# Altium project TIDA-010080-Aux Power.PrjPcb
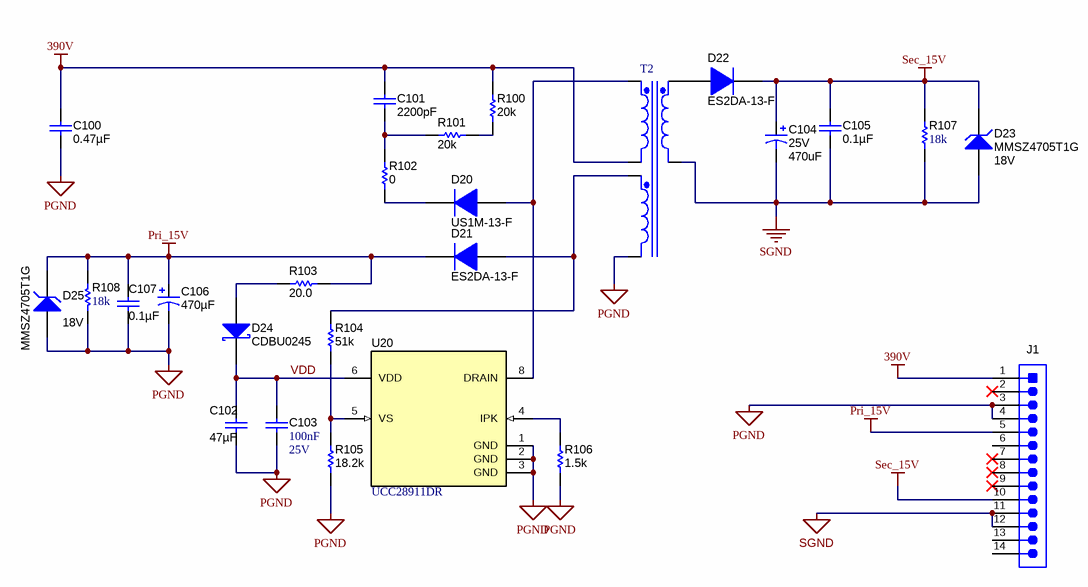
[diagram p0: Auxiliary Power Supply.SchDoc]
EVM_Orderable: N/A; PCB_Rev: E1; PRJ_Customer: Public Release; PRJ_Engineer: Max Wang; PRJ_Number: TIDA-010080-Aux; SCH_Rev: E1; TechSupport: http://www.ti.com/support; TID: TIDA-010080-Aux
3 sheets, 32 parts. Net scope: global (net labels, ports and power ports of the same name join across sheets).
Board file: Auxiliary Power Supply.pcbdoc
Sheets:
  Auxiliary Power Supply.SchDoc
  CoverSheet.SchDoc
  Hardware.SchDoc

## Sheet Auxiliary Power Supply.SchDoc
size 431 x 279 mm; PageSetup: Record=PageOptions¦CenterHorizontal=True¦CenterVertical=True¦PrintScale=1.00¦XCorrection=1.00¦YCorrection=1.00¦PrintKind=0¦BorderSize=5000000¦LeftOffset=0¦BottomOffset=0¦Orientation=2¦PaperLength=1000¦PaperWidth=1000¦Scale=100¦PaperSource=15¦PrintQuality=600¦MediaType=1¦DitherType=10¦PaperKind=Letter¦PrintScaleMode=1; TID#: TIDA-010081_AUX

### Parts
C100  ValueDisplayed: 0.47µF  [ECWFD_1260x650x1270]  (hidden comment: ECW-FD2W474Q1)
C101  ValueDisplayed: 2200pF  [1206]  (hidden comment: GRM31BR72J222KW01L)
C102  ValueDisplayed: 47µF  [1206_190]  (hidden comment: C3216X5R1E476M160AC)
C103  Cap_F: 100nF  VDC_V: 25V  [0603]  (hidden comment: GRM188R71E104KA01D)
C104  VDC_V: 25V  ValueDisplayed: 470uF  [Chemi-Con_1000x1600]  (hidden comment: ELXZ250ELL471MJ16S)
C105  ValueDisplayed: 0.1µF  [0603]  (hidden comment: C0603C104K3RACTU)
C106  ValueDisplayed: 470µF  [Chemi-Con_1000x1600]  (hidden comment: ELXZ250ELL471MJ16S)
C107  ValueDisplayed: 0.1µF  [0603]  (hidden comment: C0603C104K3RACTU)
D20  US1M-13-F  [SMA]
D21  ES2DA-13-F  [SMA]
D22  ES2DA-13-F  [SMA]
D23  MMSZ4705T1G  value 18V  [SOD-123]
D24  CDBU0245  [SOD-523F]
D25  MMSZ4705T1G  value 18V  [SOD-123]
J1  TSW-114-08-L-S-RA  [TE_4-644694-4]  (value not drawn)
R100  ValueDisplayed: 20k  [1206]  (hidden comment: CRCW120620K0JNEA)
R101  ValueDisplayed: 20k  [1206]  (hidden comment: CRCW120620K0JNEA)
R102  ValueDisplayed: 0  [0805_HV]  (hidden comment: CRCW08050000Z0EA)
R103  ValueDisplayed: 20.0  [1206L]  (hidden comment: CRCW120620R0FKEA)
R104  ValueDisplayed: 51k  [0603]  (hidden comment: CRCW060351K0JNEA)
R105  ValueDisplayed: 18.2k  [0805_HV1]  (hidden comment: CRCW080518K2FKEA)
R106  ValueDisplayed: 1.5k  [0603]  (hidden comment: CRCW06031K50JNEA)
R107  ValueDisplayed: 18k  [0603]  (hidden comment: CRCW060318K0JNEA)
R108  ValueDisplayed: 18k  [0603]  (hidden comment: CRCW060318K0JNEA)
T2  750344399  [Fly_T1]  (value not drawn)
U20  UCC28911DR  [D0007A_N]

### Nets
390V: C100.1 C101.1 J1.1 R100.2 T2.4(Sec1-)
PGND: C100.2 C102.2 C103.2 C106.2(-) C107.2 D25.2(A) J1.3 J1.4 R105.1 R106.1 R108.1 T2.6(Sec2-) U20.1(GND) U20.2(GND) U20.3(GND)
Pri_15V: C106.1(+) C107.1 D21.1(K) D25.1(K) J1.5 R103.1 R108.2
Sec_15V: C104.1(+) C105.1 D22.1(K) D23.1(K) J1.10 R107.2
SGND: C104.2(-) C105.2 D23.2(A) J1.11 J1.12 R107.1 T2.2(Pri-)
VDD: C102.1 C103.1 D24.1(K) U20.6(VDD)
NetC101_2: C101.2 R101.2 R102.2
NetD20_1: D20.1(K) R102.1
NetD20_2: D20.2(A) T2.3(Sec1+) U20.8(DRAIN)
NetD21_2: D21.2(A) R104.2 T2.5(Sec2+)
NetD22_2: D22.2(A) T2.1(Pri+)
NetD24_2: D24.2(A) R103.2
NetR100_1: R100.1 R101.1
NetR104_1: R104.1 R105.2 U20.5(VS)
NetR106_2: R106.2 U20.4(IPK)

Not connected (* = marked no-connect by the designer): J1 2* 6 7* 8* 9* 13 14

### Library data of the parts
C100 = ECW-FD2W474Q1: CAP, Film, 0.47 µF, 450 V, +/- 10%, TH; Manufacturer: Panasonic; Polarized: N; CompType: Capacitor; Value: 0.47uF; U/M: EA; Cap_F: 0.00000047; Tolerance_%: 10; Value1: Unknown; VDC_V: 450; Value2: 450V; TaMin_C: -40; TaMax_C: 110; Cap_Case: 12.6x6.5x12.7mm; AEC Category: Q200
C101 = GRM31BR72J222KW01L: CAP, CERM, 2200 pF, 630 V,+/- 10%, X7R, 1206; Manufacturer: MuRata; Polarized: N; CompType: Capacitor; Value: 2200pF; U/M: EA; Cap_F: 0.0000000022; Tolerance_%: 10; VDC_V: 630; Value2: 630V; TaMin_C: -55; TaMax_C: 125; SizeArea_mm2: 5.12; SizeAreaWB_mm2: 10.92; SizeX_mm: 3.2; SizeY_mm: 1.6; SizeZ_mm: 1.35; AEC Category: Q200; Green_Lifecycle: Not Set; Green_REACh: Incomplete
C102 = C3216X5R1E476M160AC: CAP, CERM, 47 µF, 25 V,+/- 20%, X5R, 1206; Manufacturer: TDK; Polarized: N; CompType: Capacitor; Value: 47uF; U/M: EA; Cap_F: 0.000047; Tolerance_%: 20; VDC_V: 25; Value2: 25V; TaMin_C: -55; TaMax_C: 85; Cap_Case: 1206; SizeArea_mm2: 5.12; SizeAreaWB_mm2: 10.92; SizeX_mm: 3.2; SizeY_mm: 1.6; SizeZ_mm: 1.9; AEC Category: Q200; Green_Lifecycle: Active; Green_REACh: Passed
C103 = CMP-0007404-4: CAP, CERM, 0.1 uF, 25 V, +/- 10%, X7R, 0603; Manufacturer: MuRata; TaMin_C: -55°C; Polarized: N; SizeAreaWB_mm2: 4.68; Value1: Unknown; U/M: EA; Value: 0.1uF; TaMax_C: 125°C; SizeZ_mm: 1; SizeX_mm: 1.6; SizeY_mm: 0.8; SizeArea_mm2: 1.28; AEC Category: Q200
C104 = CMP-0010480-1: CAP, AL, 470 uF, 25 V, +/- 20%, AEC-Q200 Grade 2, TH; Manufacturer: Chemi-Con; TaMin_C: -55°C; Polarized: Y; SizeAreaWB_mm2: 144; Value1: Unknown; U/M: EA; Value: 470uF; TaMax_C: 105°C; SizeZ_mm: 17.5; SizeX_mm: 10; Cap_Case: 10x16mm; SizeArea_mm2: 100; CompType: Capacitor; Cap_F: 470µF; IRMS_A: 1.05A; AEC Grade: 2; AEC Category: Q200
C105 C107 = C0603C104K3RACTU: CAP, CERM, 0.1 µF, 25 V,+/- 10%, X7R, 0603; Manufacturer: Kemet; Polarized: N; CompType: Capacitor; Value: 0.1uF; U/M: EA; Cap_F: 0.0000001; Tolerance_%: 10; VDC_V: 25; Value2: 25V; TaMin_C: -55; TaMax_C: 125; SizeArea_mm2: 1.28; SizeAreaWB_mm2: 4.68; SizeX_mm: 1.6; SizeY_mm: 0.8; SizeZ_mm: 1; AEC Category: Q200; Green_Lifecycle: Active; Green_REACh: Passed
C106 = ELXZ250ELL471MJ16S: CAP, AL, 470 µF, 25 V, +/- 20%, AEC-Q200 Grade 2, TH; Manufacturer: Chemi-Con; Polarized: Y; CompType: Capacitor; Value: 470uF; U/M: EA; Cap_F: 0.00047; Tolerance_%: 20; VDC_V: 25; Value2: 25V; IRMS_A: 1.05; TaMin_C: -55; TaMax_C: 105; Cap_Case: 10x16mm; SizeAreaWB_mm2: 144; SizeArea_mm2: 100; SizeX_mm: 10; SizeZ_mm: 17.5; AEC Category: Q200; AEC Grade: 2
D20 = US1M-13-F: Diode, Ultrafast, 1000 V, 1 A, SMA; Manufacturer: Diodes Inc.; U/M: EA; Vf_V: 1.7; Value: 1000V; Value1: 1A; Value2: 1.7V; Io_A: 1; Vr_V: 1000; TJmax_C: 150; RJC_CperW: 30; SizeAreaWB_mm2: 37.3428; SizeArea_mm2: 16.3228; SizeX_mm: 5.59; SizeY_mm: 2.92; SizeZ_mm: 2.87; AEC Category: Q101
D21 D22 = ES2DA-13-F: Diode, Superfast Rectifier, 200 V, 2 A, SMA; Manufacturer: Diodes Inc.; U/M: EA; Vf_V: 0.92; Value: 200V; Value1: 2A; Value2: 0.92V; Io_A: 2; Vr_V: 200; TJmax_C: 150; RJC_CperW: 20; SizeAreaWB_mm2: 37.3428; SizeArea_mm2: 16.3228; SizeX_mm: 5.59; SizeY_mm: 2.92; SizeZ_mm: 2.87; AEC Category: Q101; Green_Lifecycle: Not Set; Green_REACh: Incomplete
D23 D25 = MMSZ4705T1G: Diode, Zener, 18 V, 500 mW, SOD-123; Manufacturer: ON Semiconductor; SymbolCreator: a0412235; U/M: EA; Power_W: 0.5; Vz_V: 18; Value1: 0.5W; RJA_CperW: 340; SizeAreaWB_mm2: 13.095; SizeArea_mm2: 6.545; SizeX_mm: 3.85; SizeY_mm: 1.7; SizeZ_mm: 1.35; AEC Category: Q101
D24 = CDBU0245: Diode, Schottky, 50 V, 0.2 A, SOD-523F; Manufacturer: Comchip Technology; U/M: EA; Vf_V: 0.55; Value: 50V; Value1: 0.2A; Value2: 0.55V; Io_A: 0.2; Vr_V: 50; TJmax_C: 125; SizeAreaWB_mm2: 5.13; SizeArea_mm2: 1.53; SizeX_mm: 1.7; SizeY_mm: 0.9; SizeZ_mm: 0.85; AEC Category: Q101; AEC Qualified: N; Green_Lifecycle: Not Set; Green_REACh: Incomplete
J1 = 4-644694-4: Header, 100 mil, 14x1, Gold, R/A, TH; Manufacturer: Samtec; SymbolCreator: a0411947; Pitch_mm: 2.54; Gender: Male; Shrouded: N; Row_Count: 1; Cert_CSA: Y
R100 R101 = CRCW120620K0JNEA: RES, 20 k, 5%, 0.25 W, 1206; Manufacturer: Vishay-Dale; CompType: Resistor; Value: 20k; Res_ohm: 20000; Value_Code: 20k0; Tolerance_%: 5; Power_W: 0.25; Value2: 0.25W; VDC_V: 200; TempCo: 200 ppm/C; SizeArea_mm2: 5.12; SizeX_mm: 3.2; SizeY_mm: 1.6; SizeZ_mm: 1.35; EIA_Code: E24; U/M: EA; AEC Category: Q200; Green_Lifecycle: Active; Green_REACh: Passed
R102 = CRCW08050000Z0EA: RES, 0, 5%, 0.125 W, 0805; Manufacturer: Vishay-Dale; CompType: Resistor; Value: 0; Value_Code: 0000; Tolerance_%: 5; Power_W: 0.125; Value2: 0.125W; VDC_V: 150; TempCo: 200 ppm/C; SizeArea_mm2: 2.5; SizeX_mm: 2; SizeY_mm: 1.25; SizeZ_mm: 1.45; EIA_Code: E24; U/M: EA; AEC Category: Q200; Green_Lifecycle: Active; Green_REACh: Passed
R103 = CRCW120620R0FKEA: RES, 20.0, 1%, 0.25 W, 1206; Manufacturer: Vishay-Dale; CompType: Resistor; Value: 20.0; Res_ohm: 20; Value_Code: 20R0; Tolerance_%: 1; Power_W: 0.25; Value2: 0.25W; VDC_V: 200; TempCo: 100 ppm/C; SizeArea_mm2: 5.12; SizeX_mm: 3.2; SizeY_mm: 1.6; SizeZ_mm: 1.35; EIA_Code: E96; U/M: EA; AEC Category: Q200
R104 = CRCW060351K0JNEA: RES, 51 k, 5%, 0.1 W, 0603; Manufacturer: Vishay-Dale; CompType: Resistor; Value: 51k; Res_ohm: 51000; Value_Code: 51k0; Tolerance_%: 5; Power_W: 0.1; Value2: 0.1W; VDC_V: 75; TempCo: 200 ppm/C; SizeArea_mm2: 1.28; SizeX_mm: 1.6; SizeY_mm: 0.8; SizeZ_mm: 1; EIA_Code: E24; U/M: EA; AEC Category: Q200; Green_Lifecycle: Active; Green_REACh: Passed
R105 = CRCW080518K2FKEA: RES, 18.2 k, 1%, 0.125 W, 0805; Manufacturer: Vishay-Dale; CompType: Resistor; Value: 18.2k; Res_ohm: 18200; Value_Code: 18k2; Tolerance_%: 1; Power_W: 0.125; Value2: 0.125W; VDC_V: 150; TempCo: 100 ppm/C; SizeArea_mm2: 2.5; SizeX_mm: 2; SizeY_mm: 1.25; SizeZ_mm: 1.45; EIA_Code: E96; U/M: EA; AEC Category: Q200
R106 = CRCW06031K50JNEA: RES, 1.5 k, 5%, 0.1 W, 0603; Manufacturer: Vishay-Dale; CompType: Resistor; Value: 1.5k; Res_ohm: 1500; Value_Code: 1k50; Tolerance_%: 5; Power_W: 0.1; Value2: 0.1W; VDC_V: 75; TempCo: 200 ppm/C; SizeArea_mm2: 1.28; SizeX_mm: 1.6; SizeY_mm: 0.8; SizeZ_mm: 1; EIA_Code: E24; U/M: EA; AEC Category: Q200; Green_Lifecycle: Active; Green_REACh: Passed
R107 = CMP-0025727-4: RES, 18 k, 5%, 0.1 W, AEC-Q200 Grade 0, 0603; Manufacturer: Vishay-Dale; Power_W: 100mW; TempCo: 200 ppm/C; Value_Code: 18k0; Value: 18k; EIA_Code: E24; SizeX_mm: 1.6; SizeY_mm: 0.8; SizeZ_mm: 1; Value2: 0.1W; SizeArea_mm2: 1.28; AEC Qualified: Y; VDC_V: 75V; AEC Category: Q200; AEC Grade: 0
R108 = CMP-0025727-4: RES, 18 k, 5%, 0.1 W, AEC-Q200 Grade 0, 0603; Manufacturer: Vishay-Dale; Power_W: 100mW; TempCo: 200 ppm/C; Value_Code: 18k0; Value: 18k; EIA_Code: E24; SizeX_mm: 1.6; SizeY_mm: 0.8; SizeZ_mm: 1; Value2: 0.1W; SizeArea_mm2: 1.28; CompType: Resistor; AEC Qualified: Y; VDC_V: 75V; AEC Category: Q200; AEC Grade: 0
T2 = Trans3 Ideal: 750344399 Wuth; Manufacturer: Wurth
U20 = CMP-0074093-2: 700V Flyback Switcher with Constant-Voltage Constant-Current and Primary-side Regulation, D0007A (SOIC-7); Alternate Manufacturer: Texas Instruments; SizeAreaWB_mm2: 55.2; U/M: EA; SizeZ_mm: 1.75; SizeX_mm: 6.0; SizeY_mm: 4.9; SizeArea_mm2: 29.4; CompType: IC; AEC Category: Q200; AEC Qualified: N

## Sheet CoverSheet.SchDoc
size 431 x 279 mm; Date: Not shown in title block; ApprovedBy: Not shown in title block; CheckedBy: Not shown in title block; Author: Not shown in title block; CompanyName: Not shown in title block; Engineer: Not shown in title block; Organization: Not shown in title block; Address1: Not shown in title block; Address2: Not shown in title block; Address3: Not shown in title block; Address4: Not shown in title block; DocumentNumber: 1; Revision: Use project parameter SCH_Rev; SheetNumber: 1; SheetTotal: 3; PageSetup: Record=PageOptions¦CenterHorizontal=True¦CenterVertical=True¦PrintScale=1.00¦XCorrection=1.00¦YCorrection=1.00¦PrintKind=0¦BorderSize=5000000¦LeftOffset=0¦BottomOffset=0¦Orientation=2¦PaperLength=1000¦PaperWidth=1000¦Scale=100¦PaperSource=15¦PrintQuality=600¦MediaType=1¦DitherType=10¦PaperKind=Letter¦PrintScaleMode=1
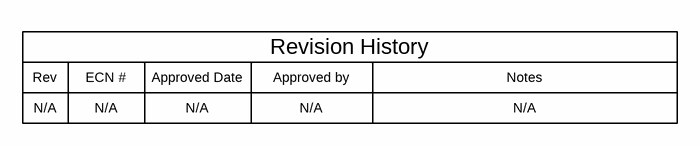
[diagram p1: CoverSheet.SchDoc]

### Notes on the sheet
- Rev
- N/A
- ECN #
- Approved Date
- Approved by
- Revision History
- Notes

## Sheet Hardware.SchDoc
size 431 x 279 mm; Date: Not shown in title block; ApprovedBy: Not shown in title block; CheckedBy: Not shown in title block; Author: Not shown in title block; CompanyName: Not shown in title block; Engineer: Not shown in title block; Organization: Not shown in title block; Address1: Not shown in title block; Address2: Not shown in title block; Address3: Not shown in title block; Address4: Not shown in title block; DocumentNumber: 3; Revision: Use project parameter SCH_Rev; SheetNumber: 3; SheetTotal: 3; PageSetup: Record=PageOptions¦CenterHorizontal=True¦CenterVertical=True¦PrintScale=1.00¦XCorrection=1.00¦YCorrection=1.00¦PrintKind=0¦BorderSize=5000000¦LeftOffset=0¦BottomOffset=0¦Orientation=2¦PaperLength=1000¦PaperWidth=1000¦Scale=100¦PaperSource=15¦PrintQuality=600¦MediaType=1¦DitherType=10¦PaperKind=Letter¦PrintScaleMode=1
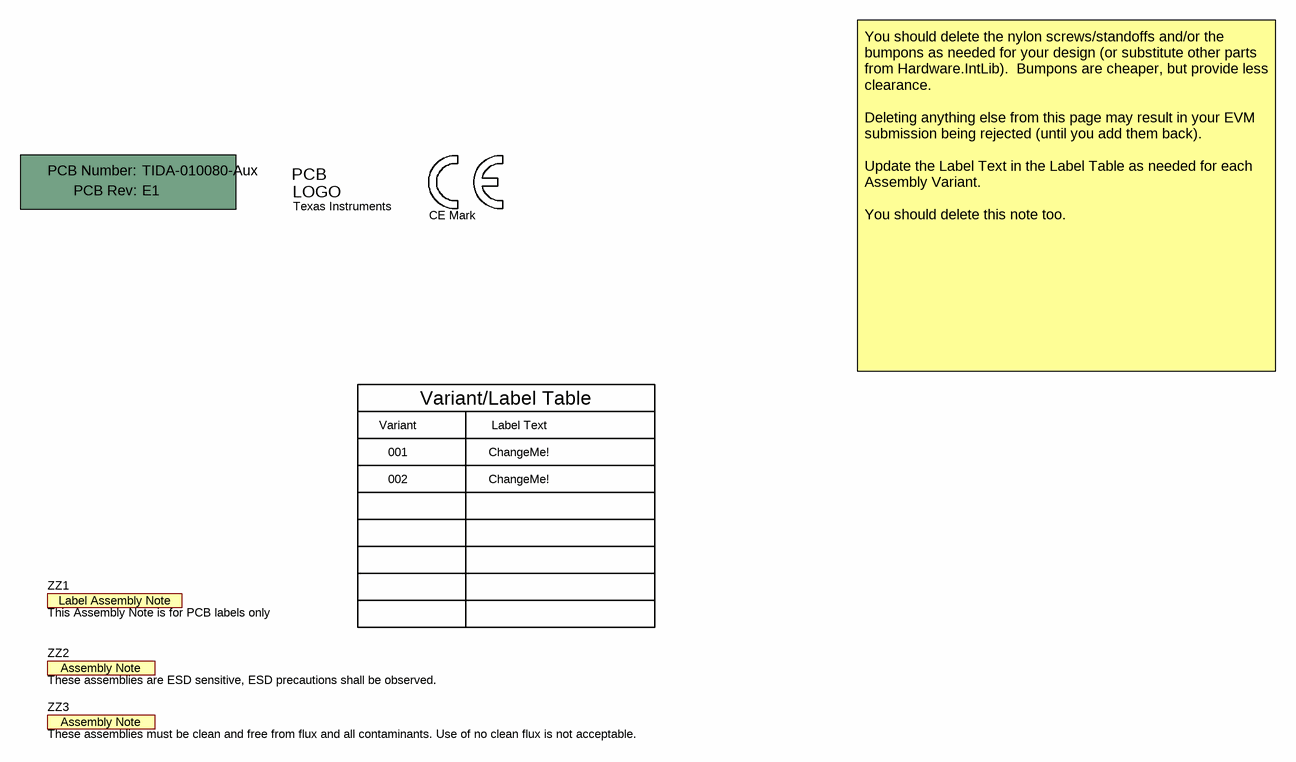
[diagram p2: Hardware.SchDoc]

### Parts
!PCB  Printed Circuit Board  (value not drawn)  (mechanical)
Logo1  Texas Instruments  [TI_Stacked_Overlay_Small]  (no BOM)
Logo2  CE Mark  [CE_Mark_5mm]  (no BOM)
ZZ1  This Assembly Note is for PCB labels only  [AssemblyNoteLabel]  (no BOM)
ZZ2  These assemblies are ESD sensitive, ESD precautions shall be observed.  [AssemblyNote]  (no BOM)
ZZ3  These assemblies must be clean and free from flux and all contaminants. Use of no clean flux is not acceptable.  [AssemblyNote]  (no BOM)

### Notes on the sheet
- Variant
- Variant/Label Table
- Label Text
- You should delete the nylon screws/standoffs and/or the bumpons as needed for your design (or substitute other parts from Hardware.IntLib).  Bumpons are cheaper, but provide less clearance.
  Deleting anything else from this page may result in your EVM submission being rejected (until you add them back).
  Update the Label Text in the Label Table as needed for each Assembly Variant.
  You should delete this note too.
- 001
- 002
- ChangeMe!

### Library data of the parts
!PCB = CMP-0003618-2: Manufacturer: Any; PartNumber: TIDA-010080-Aux
Logo1 = CMP-0074838-1: Texas Instrument Corporate Signature; SymbolCreator: a0412235; Lib Reference: TI_Logo; Library Reference: Logo
Logo2 = CMP-0074844-1: SymbolCreator: a0412235
ZZ1 = CMP-0003616-3
ZZ2 = CMP-0077236-1
ZZ3 = CMP-0077237-1

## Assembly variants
001: all parts fitted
